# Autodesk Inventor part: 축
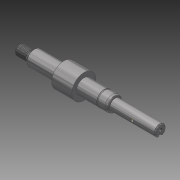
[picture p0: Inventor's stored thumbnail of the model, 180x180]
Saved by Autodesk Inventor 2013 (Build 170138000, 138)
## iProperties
Created: 2016-08
Part Number: 축
Material: 강철, 탄소
Document SubType Name: Modeling
Designer: mduedu
Density: 7.87 g/cm^3
Author: mduedu
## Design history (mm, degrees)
sketch "스케치1"
  geometry: L1 (-72.5, 0)-(72.5, 0); L2 (-72.5, 0)-(-72.5, 5); L3 (-72.5, 5)-(-58.5, 5); L4 (-58.5, 5)-(-58.5, 7.5); L5 (-58.5, 7.5)-(25.855, 7.5); L6 (27.5, 6.55)-(27.5, 5.5); L7 (27.5, 5.5)-(72.5, 5.5); L8 (72.5, 5.5)-(72.5, 0); L9 (27.5, 6.55)-(25.855, 7.5); 2 further points
  constraints: 18 end point, 5 parallel, 2 perpendicular, 1 coincident, 1 horizontal, 1 midpoint
  dimensions: "d0" = 145 distance of L1.start L1.end; "d2" = 14 distance of L2.end L3.end; "d4" = 10 diameter of L3 L1; "d5" = 15 diameter of L5 L1; "d6" = 11 diameter of L7 L1; "d63" = 45 distance between parallel lines of L6 L8; "d64" = 30 deg angle of L5 L9; "d65" = 13.1 diameter of L6.start L1
revolve "회전1" sketch "스케치1" stored, may be unused: angle "d7" = 90 deg
sketch "스케치2"
  geometry: L1 (-58.5, -5)-(-58.5, 5) reference; L2 (72.5, -5.5)-(72.5, 5.5) reference; L3 (-58.5, 0)-(72.5, 0); L4 (-60.5, 4.5)-(-60.5, 5); L5 (-60.5, 5)-(-58.5, 5); L6 (-58.5, 5)-(-58.5, 4.5); L7 (-60.5, 4.5)-(-58.5, 4.5); 1 further point
  constraints: 10 end point, 2 midpoint, 1 parallel, 1 perpendicular, 1 point on line
  dimensions: "d8" = 2 distance of L4.end L5.end; "d10" = 10 diameter of L5 L3; "d11" = 9 diameter of L7 L3
revolve "회전2" sketch "스케치2" stored, may be unused: angle "d12" = 90 deg
node "작업 평면1"
sketch "스케치3"
  geometry: C1 r 12 at (0, 0); 1 further point
  constraints: 1 centre point, 1 coincident
  dimensions: "d15" = 24 diameter of C1
extrude "돌출1" join sketch "스케치3" distance "d16" = 20; taper "d17" = 0 deg
sketch "스케치5"
  geometry: L1 (-72.5, -5)-(-72.5, 5) reference; L2 (72.5, -5.5)-(72.5, 5.5) reference; L3 (-72.5, 0)-(72.5, 0); L4 (-8.5, 7.5)-(25.855, 7.5) reference; L5 (12.65, 7.5)-(11.5, 7.5); L6 (11.5, 7.5)-(11.5, 7.15); L7 (11.5, 7.15)-(12.65, 7.15); L8 (12.65, 7.15)-(12.65, 7.5); L9 (-8.5, -12)-(-8.5, 12) reference; 1 further point
  constraints: 10 end point, 2 midpoint, 2 parallel, 1 horizontal, 1 perpendicular, 1 point on line
  dimensions: "d20" = 1.15 distance between parallel lines of L8 L6; "d21" = 14.3 diameter of L7 L3; "d82" = 20 distance between parallel lines of L9 L6
revolve "회전3" sketch "스케치5" stored, may be unused: angle "d22" = 90 deg
node "작업 평면3"
sketch "스케치6"
  geometry: L1 (-6.5, 2)-(-22.5, 2); L2 (-22.5, 2)-(-22.5, -2); L3 (-22.5, -2)-(-6.5, -2); L4 (-22.5, 5.5)-(-22.5, -5.5) reference; A1 r 2 centre (-6.5, 0) between (-6.5, -2) and (-6.5, 2); 2 further points
  constraints: 6 end point, 2 midpoint, 2 point on circle, 2 tangent, 1 centre point, 1 horizontal, 1 horizontal alignment, 1 parallel, 1 perpendicular
  dimensions: "d23" = 4 distance between parallel lines of L3 L1; "d62" = 18 dimension on A1 L2
extrude "돌출2" cut sketch "스케치6" distance "d25" = 2.5; taper "d26" = 0 deg
feature "스레드1" dims "d27" = 10, "d28" = 0
chamfer "모따기5" distance "d41" = 0.5; stored, may be unused: second distance "d42" = 2, angle "d43" = 45 deg
chamfer "모따기7" distance "d47" = 1; stored, may be unused: second distance "d48" = 2, angle "d49" = 45 deg
chamfer "모따기8" distance "d50" = 1; stored, may be unused: second distance "d51" = 2, angle "d52" = 45 deg
sketch "스케치8"
  geometry: 1 further point
hole "구멍1" sketch "스케치8" at (2, 3.5) diameter "d53" = 3.242; stored, may be unused: countersink angle "d57" = 90 deg, drill point angle "d59" = 120 deg; dims "d54" = 10, "d55" = 4, "d56" = 2, "d58" = 12
fillet "모깎기1" dims "d66" = 4, "d67" = 0.5
sketch "스케치10"
  geometry: L1 (-27.5, 5.5)-(-71.5, 5.5) reference; L2 (-51, 5.5)-(-49.5, 4); L3 (-49.5, 4)-(-49.5, 5.5); L4 (-72.5, -4.5)-(-72.5, 4.5) reference; 3 further points
  constraints: 4 end point, 1 midpoint, 1 perpendicular, 1 point on line
  dimensions: "d77" = 45 deg angle of L2 L3; "d78" = 3 diameter of L2.start L3; "d80" = 23 distance between parallel lines of L4 L3
revolve "회전4" sketch "스케치10" stored, may be unused: angle "d81" = 90 deg
node "작업점1"
node "솔리드1"
other parameters: "d13" = -44
